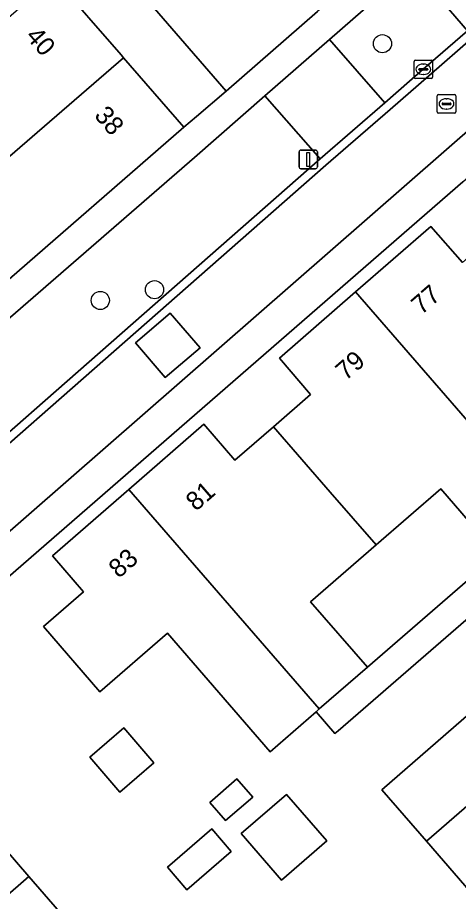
# Model space of a CAD drawing. Extents: x 155887 to 156869, y 383880 to 384678.
# Drawn here: x 156348.66 to 156372.39, y 384049.47 to 384097.03 of the extents above; entities that cross this region are included whole.
import ezdxf

# ---------------------------------------------------------------- set-up
doc = ezdxf.new("R2010")
doc.units = 0
for name, color, linetype in [('IMGEO_Boom', 7, 'Continuous'), ('IMGEO_Erf', 7, 'Continuous'), ('IMGEO_Kolk', 7, 'Continuous'), ('IMGEO_Lichtmast', 7, 'Continuous'), ('IMGEO_Pand', 7, 'Continuous'), ('IMGEO_Pand_nummerreeks', 7, 'Continuous'), ('IMGEO_Parkeervlak_open', 7, 'Continuous'), ('IMGEO_Rijbaan_lokaal_gesloten', 7, 'Continuous'), ('IMGEO_Rijbaan_lokaal_open', 7, 'Continuous'), ('IMGEO_Rioolput', 7, 'Continuous'), ('IMGEO_Verkeerseiland_groen', 7, 'Continuous'), ('IMGEO_Voetpad_open', 7, 'Continuous')]:
    doc.layers.add(name, color=color, linetype=linetype)

msp = doc.modelspace()

# ---------------------------------------------------------------- linework, layer by layer
at = {"layer": 'IMGEO_Boom'}
for centre in [(156368.307, 384095.623), (156356.032, 384082.386), (156353.112, 384081.809)]:
    msp.add_circle(centre, 0.489, dxfattribs=at)
at = {"layer": 'IMGEO_Erf'}
for points in [[(156359.895, 384093.079), (156326.654, 384131.386), (156324.334, 384129.488), (156328.231, 384124.995), (156331.964, 384120.692), (156335.697, 384116.388), (156339.43, 384112.085), (156343.163, 384107.781), (156346.896, 384103.477), (156350.629, 384099.174), (156354.231, 384095.022), (156354.362, 384094.871), (156357.607, 384091.13), (156358.294, 384091.715)], [(156371.444, 384071.664), (156367.963, 384068.649), (156364.437, 384065.594), (156367.493, 384062.066), (156374.5, 384068.136)], [(156354.17, 384055.348), (156352.543, 384057.228), (156354.371, 384058.811), (156355.999, 384056.932)], [(156359.006, 384054.799), (156360.468, 384056.066), (156361.321, 384055.082), (156359.859, 384053.815)], [(156362.865, 384050.609), (156360.694, 384053.117), (156363.134, 384055.23), (156365.306, 384052.723)], [(156356.729, 384051.307), (156359.111, 384053.37), (156360.162, 384052.156), (156357.78, 384050.093)]]:
    msp.add_lwpolyline(points, close=True, dxfattribs=at)
for points in [[(156372.634, 384088.199), (156329.142, 384050.413), (156328.149, 384048.934), (156360.938, 384011.241), (156362.61, 384011.694), (156406.195, 384049.568)], [(156375.63, 384067.064), (156365.923, 384058.654), (156365.749, 384058.503), (156364.733, 384059.675), (156362.251, 384057.525), (156356.73, 384063.898), (156353.094, 384060.749), (156350.052, 384064.27), (156352.209, 384066.134), (156350.539, 384068.067), (156354.642, 384071.631), (156358.686, 384075.144), (156360.363, 384073.211), (156362.432, 384075.006), (156364.439, 384076.748), (156362.758, 384078.696), (156366.855, 384082.263), (156370.907, 384085.791), (156372.61, 384083.854)], [(156374.189, 384022.144), (156365.338, 384014.487), (156361.085, 384019.381), (156356.957, 384024.132), (156352.823, 384028.89), (156348.703, 384033.632), (156344.574, 384038.383), (156340.448, 384043.132), (156336.32, 384047.883), (156332.03, 384052.82), (156340.861, 384060.488), (156342.001, 384061.483), (156347.913, 384066.639), (156348.044, 384066.488), (156342.126, 384061.327), (156340.992, 384060.338), (156345.147, 384055.557), (156349.27, 384050.813), (156353.399, 384046.062), (156357.534, 384041.306), (156361.657, 384036.563), (156365.79, 384031.808), (156369.924, 384027.051), (156374.058, 384022.295)], [(156373.088, 384049.931), (156370.676, 384052.704), (156368.265, 384055.477), (156378.205, 384064.093)]]:
    msp.add_lwpolyline(points, dxfattribs=at)
at = {"layer": 'IMGEO_Kolk'}
for p, q in [((156370.008, 384093.821), (156370.008, 384094.673)), ((156370.083, 384094.747), (156370.935, 384094.747)), ((156371.009, 384094.673), (156371.009, 384093.821)), ((156370.267, 384094.241), (156370.267, 384094.253)), ((156370.705, 384094.204), (156370.307, 384094.204)), ((156370.31, 384094.29), (156370.708, 384094.29)), ((156370.496, 384094.527), (156370.521, 384094.527)), ((156370.751, 384094.253), (156370.751, 384094.241)), ((156370.935, 384093.747), (156370.083, 384093.747)), ((156370.519, 384093.967), (156370.494, 384093.967))]:
    msp.add_line(p, q, dxfattribs=at)
for points in [[(156370.008, 384093.821), (156370.008, 384094.673)], [(156370.083, 384094.747), (156370.935, 384094.747)], [(156371.009, 384094.673), (156371.009, 384093.821)], [(156370.935, 384093.747), (156370.083, 384093.747)]]:
    msp.add_lwpolyline(points, dxfattribs=at)
for centre, radius, start, end in [((156370.085, 384094.671), 0.0765, 91.552, 178.448), ((156370.085, 384094.671), 0.0765, 91.552, 178.448), ((156370.933, 384094.671), 0.0765, 1.552, 88.448), ((156370.933, 384094.671), 0.0765, 1.552, 88.448), ((156370.307, 384094.25), 0.0403, 85.8775, 175.7526), ((156370.304, 384094.24), 0.0366, 178.938, 274.7102), ((156370.708, 384094.247), 0.043, 264.8664, 352.4533), ((156370.712, 384094.252), 0.0386, 1.7309, 96.639), ((156370.085, 384093.823), 0.0765, 181.552, 268.448), ((156370.085, 384093.823), 0.0765, 181.552, 268.448), ((156370.933, 384093.823), 0.0765, 271.552, 358.448), ((156370.933, 384093.823), 0.0765, 271.552, 358.448)]:
    msp.add_arc(centre, radius, start, end, dxfattribs=at)
for centre, major_axis, ratio, start_param, end_param in [((156370.495, 384094.247), (-0.387, 0.002), 0.722429, 4.712389, 7.853982), ((156370.52, 384094.247), (-0.39, 0.002), 0.717154, 1.570796, 4.712389)]:
    msp.add_ellipse(centre, major_axis=major_axis, ratio=ratio, start_param=start_param, end_param=end_param, dxfattribs=at)
at = {"layer": 'IMGEO_Lichtmast'}
for p, q in [((156363.814, 384088.997), (156363.814, 384089.797)), ((156363.814, 384089.797), (156363.814, 384088.997)), ((156363.914, 384089.897), (156364.704, 384089.897)), ((156364.704, 384089.897), (156363.914, 384089.897)), ((156364.804, 384089.797), (156364.804, 384088.997)), ((156364.804, 384088.997), (156364.804, 384089.797)), ((156364.704, 384088.897), (156363.914, 384088.897)), ((156363.914, 384088.897), (156364.704, 384088.897))]:
    msp.add_line(p, q, dxfattribs=at)
msp.add_lwpolyline([(156364.234, 384089.772), (156364.384, 384089.772), (156364.384, 384089.022), (156364.234, 384089.022), (156364.234, 384089.772)], dxfattribs=at)
for centre, start, end in [((156363.914, 384089.797), 90, 180), ((156363.914, 384089.797), 90, 180), ((156364.704, 384089.797), 0, 90), ((156364.704, 384089.797), 360, 90), ((156363.914, 384088.997), 180, 270), ((156363.914, 384088.997), 180, 270), ((156364.704, 384088.997), 270, 0), ((156364.704, 384088.997), 270, 0)]:
    msp.add_arc(centre, 0.1, start, end, dxfattribs=at)
at = {"layer": 'IMGEO_Pand'}
for points in [[(156350.629, 384099.174), (156342.157, 384091.821), (156345.757, 384087.691), (156344.387, 384086.497), (156344.503, 384086.363), (156354.362, 384094.871), (156354.231, 384095.022)], [(156344.503, 384086.363), (156347.788, 384082.594), (156357.607, 384091.13), (156354.362, 384094.871)], [(156377.147, 384070.429), (156379.742, 384072.677), (156374.221, 384079.051), (156377.847, 384082.195), (156374.769, 384085.744), (156372.61, 384083.854), (156370.907, 384085.791), (156366.855, 384082.263)], [(156367.963, 384068.649), (156371.444, 384071.664), (156374.5, 384068.136), (156375.963, 384069.403), (156377.147, 384070.429), (156366.855, 384082.263), (156362.758, 384078.696), (156364.439, 384076.748), (156362.432, 384075.006), (156365.492, 384071.489)], [(156367.963, 384068.649), (156365.492, 384071.489), (156362.432, 384075.006), (156360.363, 384073.211), (156358.686, 384075.144), (156354.642, 384071.631), (156364.907, 384059.826), (156367.493, 384062.066), (156364.437, 384065.594)], [(156389.421, 384068.954), (156387.012, 384071.727), (156383.293, 384068.503), (156380.718, 384071.474), (156376.94, 384068.199), (156375.63, 384067.064), (156378.205, 384064.093), (156368.265, 384055.477), (156370.676, 384052.704), (156377.035, 384058.217), (156383.154, 384063.521)], [(156354.642, 384071.631), (156350.539, 384068.067), (156352.209, 384066.134), (156350.052, 384064.27), (156353.094, 384060.749), (156356.73, 384063.898), (156362.251, 384057.525), (156364.733, 384059.675), (156364.907, 384059.826)], [(156389.421, 384068.954), (156383.154, 384063.521), (156377.035, 384058.217), (156370.676, 384052.704), (156373.088, 384049.931), (156383.025, 384058.547), (156385.6, 384055.578), (156386.908, 384056.712), (156390.686, 384059.987), (156388.111, 384062.957), (156391.794, 384066.151)], [(156354.17, 384055.348), (156355.999, 384056.932), (156354.371, 384058.811), (156352.543, 384057.228)], [(156359.006, 384054.799), (156359.859, 384053.815), (156361.321, 384055.082), (156360.468, 384056.066)], [(156340.448, 384043.132), (156349.27, 384050.813), (156345.147, 384055.557), (156336.32, 384047.883)], [(156362.865, 384050.609), (156365.306, 384052.723), (156363.134, 384055.23), (156360.694, 384053.117)], [(156356.729, 384051.307), (156357.78, 384050.093), (156360.162, 384052.156), (156359.111, 384053.37)], [(156340.448, 384043.132), (156344.574, 384038.383), (156353.399, 384046.062), (156349.27, 384050.813)]]:
    msp.add_lwpolyline(points, close=True, dxfattribs=at)
at = {"layer": 'IMGEO_Parkeervlak_open'}
msp.add_lwpolyline([(156326.165, 384056.335), (156333.68, 384061.98), (156364.949, 384089.426), (156361.976, 384092.817), (156358.182, 384089.505), (156320.966, 384057.246), (156323.169, 384054.713)], dxfattribs=at)
at = {"layer": 'IMGEO_Rijbaan_lokaal_gesloten'}
for points in [[(156421.314, 384125.367), (156424.267, 384128.023), (156420.432, 384132.447), (156418.135, 384135.097), (156376.676, 384098.955), (156373.188, 384095.976), (156370.811, 384093.901), (156368.728, 384092.09), (156365.252, 384089.08), (156333.957, 384061.613), (156326.458, 384055.98), (156326.022, 384055.616)], [(156323.513, 384054.313), (156327.105, 384050.098), (156331.018, 384054.386), (156412.184, 384125.247), (156412.191, 384125.253), (156413.195, 384126.129)]]:
    msp.add_lwpolyline(points, dxfattribs=at)
msp.add_lwpolyline([(156358.483, 384079.256), (156356.614, 384077.656), (156355.009, 384079.531), (156356.877, 384081.131)], close=True, dxfattribs=at)
at = {"layer": 'IMGEO_Rijbaan_lokaal_open'}
for points in [[(156369.05, 384101.069), (156373.448, 384104.867), (156340.225, 384143.101), (156334.608, 384138.293), (156333.088, 384136.971), (156326.654, 384131.386), (156359.895, 384093.079), (156364.8, 384097.36)], [(156424.267, 384128.023), (156424.61, 384128.331), (156420.779, 384132.75), (156418.165, 384135.765), (156417.917, 384135.517), (156376.376, 384099.303), (156372.888, 384096.324), (156370.508, 384094.247), (156368.427, 384092.437), (156364.949, 384089.426), (156333.68, 384061.98), (156326.165, 384056.335)], [(156326.022, 384055.616), (156326.458, 384055.98), (156333.957, 384061.613), (156365.252, 384089.08), (156368.728, 384092.09), (156370.811, 384093.901), (156373.188, 384095.976), (156376.676, 384098.955), (156418.135, 384135.097), (156420.432, 384132.447), (156424.267, 384128.023)]]:
    msp.add_lwpolyline(points, dxfattribs=at)
for points in [[(156376.376, 384099.303), (156373.38, 384102.774), (156369.92, 384099.753), (156372.888, 384096.324)], [(156361.976, 384092.817), (156364.949, 384089.426), (156368.427, 384092.437), (156365.454, 384095.854)], [(156356.614, 384077.656), (156358.483, 384079.256), (156356.877, 384081.131), (156355.009, 384079.531)]]:
    msp.add_lwpolyline(points, close=True, dxfattribs=at)
at = {"layer": 'IMGEO_Rioolput'}
for p, q in [((156371.256, 384091.96), (156371.256, 384092.812)), ((156371.331, 384092.886), (156372.183, 384092.886)), ((156371.744, 384092.666), (156371.769, 384092.666)), ((156372.257, 384092.812), (156372.257, 384091.96)), ((156371.515, 384092.38), (156371.515, 384092.392)), ((156371.953, 384092.343), (156371.555, 384092.343)), ((156371.558, 384092.429), (156371.956, 384092.429)), ((156371.999, 384092.392), (156371.999, 384092.38)), ((156372.183, 384091.886), (156371.331, 384091.886)), ((156371.767, 384092.106), (156371.742, 384092.106))]:
    msp.add_line(p, q, dxfattribs=at)
for points in [[(156371.256, 384091.96), (156371.256, 384092.812)], [(156371.331, 384092.886), (156372.183, 384092.886)], [(156372.257, 384092.812), (156372.257, 384091.96)], [(156372.183, 384091.886), (156371.331, 384091.886)]]:
    msp.add_lwpolyline(points, dxfattribs=at)
for centre, radius, start, end in [((156371.333, 384092.81), 0.0765, 91.552, 178.448), ((156371.333, 384092.81), 0.0765, 91.552, 178.448), ((156372.181, 384092.81), 0.0765, 1.552, 88.448), ((156372.181, 384092.81), 0.0765, 1.552, 88.448), ((156371.555, 384092.389), 0.0403, 85.8775, 175.7526), ((156371.552, 384092.379), 0.0366, 178.938, 274.7102), ((156371.956, 384092.386), 0.043, 264.8664, 352.4533), ((156371.96, 384092.391), 0.0386, 1.7309, 96.639), ((156371.333, 384091.962), 0.0765, 181.552, 268.448), ((156371.333, 384091.962), 0.0765, 181.552, 268.448), ((156372.181, 384091.962), 0.0765, 271.552, 358.448), ((156372.181, 384091.962), 0.0765, 271.552, 358.448)]:
    msp.add_arc(centre, radius, start, end, dxfattribs=at)
for centre, major_axis, ratio, start_param, end_param in [((156371.743, 384092.386), (-0.387, 0.002), 0.722429, 4.712389, 7.853982), ((156371.768, 384092.386), (-0.39, 0.002), 0.717154, 1.570796, 4.712389)]:
    msp.add_ellipse(centre, major_axis=major_axis, ratio=ratio, start_param=start_param, end_param=end_param, dxfattribs=at)
at = {"layer": 'IMGEO_Verkeerseiland_groen'}
msp.add_lwpolyline([(156372.888, 384096.324), (156369.92, 384099.753), (156365.454, 384095.854), (156368.427, 384092.437), (156370.508, 384094.247)], close=True, dxfattribs=at)
at = {"layer": 'IMGEO_Voetpad_open'}
for points in [[(156413.498, 384123.756), (156412.191, 384125.253), (156412.184, 384125.247), (156331.018, 384054.386), (156327.105, 384050.098), (156328.149, 384048.934), (156329.142, 384050.413), (156372.634, 384088.199), (156374.302, 384089.648), (156376.563, 384091.626)], [(156380.718, 384071.474), (156384.368, 384074.71), (156383.364, 384075.842), (156379.742, 384072.677), (156377.147, 384070.429), (156375.963, 384069.403), (156374.5, 384068.136), (156367.493, 384062.066), (156364.907, 384059.826), (156364.733, 384059.675), (156365.749, 384058.503), (156365.923, 384058.654), (156375.63, 384067.064), (156376.94, 384068.199)]]:
    msp.add_lwpolyline(points, close=True, dxfattribs=at)
msp.add_lwpolyline([(156373.448, 384104.867), (156369.05, 384101.069), (156364.8, 384097.36), (156359.895, 384093.079), (156358.294, 384091.715), (156357.607, 384091.13), (156347.788, 384082.594), (156339.965, 384075.806), (156338.946, 384074.921), (156332.882, 384069.66), (156324.054, 384062.007), (156319.938, 384058.416), (156320.966, 384057.246), (156358.182, 384089.505), (156361.976, 384092.817), (156365.454, 384095.854), (156369.92, 384099.753), (156373.38, 384102.774)], dxfattribs=at)

# ---------------------------------------------------------------- texts
at = {"layer": 'IMGEO_Pand_nummerreeks'}
for s, rotation, p in [('40', 310.9395, (156349.045, 384095.996)), ('38', 310.9395, (156352.742, 384091.734)), ('77', 41.0448, (156370.401, 384081)), ('79', 41.0448, (156366.327, 384077.453)), ('81', 40.9796, (156358.261, 384070.431)), ('83', 40.9779, (156354.104, 384066.819))]:
    msp.add_text(s, height=1, rotation=rotation, dxfattribs=at).set_placement(p)

doc.saveas('drawing.dxf')
